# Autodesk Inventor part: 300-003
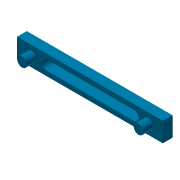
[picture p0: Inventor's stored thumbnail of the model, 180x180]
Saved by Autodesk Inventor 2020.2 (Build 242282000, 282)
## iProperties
Created: 2014-01
Part Number: 300-003
Material: Ogólny
Document SubType Name: Modeling
Designer: F.Stasiak
Density: 1 g/cm^3
Appearance: Średniobłękitna
Manager: www.cadconsulting.pl
Company: Fabian Stasiak CAD Consulting
Author: F.Stasiak
Subject: Zbiór ćwiczeń. Autodesk Inventor 2020. Kurs podstawowy
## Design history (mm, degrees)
sketch "Szkic1"
  geometry: L1 (-75, 10)-(75, 10); L2 (75, 10)-(75, -10); L3 (75, -10)-(-75, -10); L4 (-75, -10)-(-75, 10); L5 (-75, 10)-(75, -10); L6 (75, 10)-(-75, -10); 1 further point
  constraints: 12 end point, 2 equal length, 2 midpoint, 1 parallel, 1 vertical
  dimensions: "d0" = 150 distance of L2.end L3.end; "d1" = 20 distance of L1.end L2.end
extrude "Wyciągnięcie proste1" new body sketch "Szkic1" distance "d2" = 10; taper "d3" = 0 deg
sketch "Szkic2"
  geometry: L1 (-75, -10)-(75, -10) reference; L2 (-60, 0)-(60, 0); C1 r 5 at (-60, 0); C2 r 5 at (60, 0); 3 further points
  constraints: 2 centre point, 2 coincident, 2 end point, 2 horizontal alignment, 1 midpoint, 1 parallel
  dimensions: "d5" = 10 diameter of C1; "d6" = 10 diameter of C2; "d7" = 120 distance of L2.end L2.start
extrude "Wyciągnięcie proste2" join sketch "Szkic2" distance "d8" = 10; taper "d9" = 0 deg
sketch "Szkic3"
  geometry: L1 (75, 10)-(-75, 10) reference; L2 (-75, 10)-(-75, -10) reference; L3 (-45, 0)-(45, 0); L4 (-45, -5)-(45, -5); L5 (45, 5)-(-45, 5); A1 r 5 centre (-45, 0) between (-45, 5) and (-45, -5); A2 r 5 centre (45, 0) between (45, -5) and (45, 5); 3 further points
  constraints: 8 end point, 4 point on circle, 4 tangent, 2 centre point, 2 midpoint, 2 parallel, 1 coincident, 1 point on line
  dimensions: "d10" = 90 distance of L3.start L3.end; "d11" = 10 diameter of A2
extrude "Wyciągnięcie proste3" cut sketch "Szkic3" extent not by distance; stored distance "d12" = 10; taper "d13" = 0 deg
node "Bryła1"
